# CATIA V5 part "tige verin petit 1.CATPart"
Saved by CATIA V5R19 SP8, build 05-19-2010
Part number: tige verin petit 1
Bounding box of the stored display mesh (mm): x -12 to 14.392, y 48 to 54, z 107.711 to 149.853
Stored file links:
  G:\EU_thinkMotion\CFAO_2010\MMS_groupe1\MMS_groupe1\A reprendre\OK\glenerrant\glenerrant\glenerrant\tige verin petit 1.CATPart
  C:\Users\Gauthier\Documents\IFMA\Projet CFAO\Systeme.CATProduct
  G:\EU_thinkMotion\CFAO_2010\MMS_groupe1\MMS_groupe1\A reprendre\OK\glenerrant\glenerrant\glenerrant\corps verin petit 1.CATPart
  G:\EU_thinkMotion\CFAO_2010\MMS_groupe1\MMS_groupe1\A reprendre\OK\glenerrant\glenerrant\glenerrant\Bati.CATPart
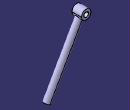
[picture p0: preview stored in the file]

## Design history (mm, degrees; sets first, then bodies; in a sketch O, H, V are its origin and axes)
Set1
  Plane1: linked copy from another document
Set2
  Point1: (-9, 51, 147)
  Point2: (17, 51, 101)
  Point3: (-9, -51, 147)
  Line1: type PtPt, FirstPoint Point3, SecondPoint Point1
  Line2: type PtPt, FirstPoint Point1, SecondPoint Point2
  Plane2: type Normal, Curve Line2, RefPoint Point1
Body1 (main body)
  Sketch1 on Plane1, origin (0, 51, 0), H (1, 0, 0), V (0, 0, 1)
    circle A1 centre (-9, 147) radius 3
    point P1 (-9, 147)
    circle A2 centre (-9, 147) radius 1.5
    point P2 (-9, 147)
    reference projected point E1 (-9, 147) from Point1
    reference projected point E2 (-9, 147) from Point1
    radius A2 = 1.5
    radius A1 = 3
    coincidence: P1 E1, P2 E2
  Pad1: profile Sketch1, direction (0, -1, 0), length 3, opposite side length 3
  Sketch2 on Plane2, origin (-65.149, 0, 115.2636), H (0, 1, 0), V (0.8706, 0, 0.4921)
    circle A1 centre (51, 64.4974) radius 2
    point P1 (51, 64.4974)
    reference projected point E1 (51, 64.4974) from Point1
    radius A1 = 2
    coincidence: P1 E1
  Pad2: profile Sketch2, direction (0.4921, 0, -0.8706), length 44, opposite side length -2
